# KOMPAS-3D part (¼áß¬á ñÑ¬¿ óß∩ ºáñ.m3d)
File: created 06.04.2016 12:01:11, last saved 22.07.2016 15:58:26.
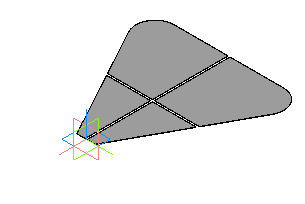
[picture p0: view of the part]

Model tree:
1. Эскиз:1
2. Операция выдавливания:1
     Толщина стенки 2 = 15; Расстояние 1 = 0.8; Расстояние 2 = 96.2519
3. Эскиз:2
4. Вырезать элемент выдавливания:1
     Толщина стенки 1 = 2; Толщина стенки 2 = 2; Расстояние 1 = 10
5. Эскиз:3
6. Вырезать элемент выдавливания:2
     Толщина стенки 1 = 2; Толщина стенки 2 = 2; Расстояние 1 = 10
